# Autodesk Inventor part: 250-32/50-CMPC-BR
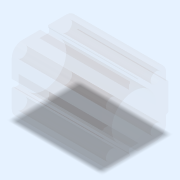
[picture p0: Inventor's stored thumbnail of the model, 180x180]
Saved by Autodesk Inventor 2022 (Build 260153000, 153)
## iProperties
Category: PARTsolutions
Company: METALWORK
Part Number: 250-32/50-CMPC-BR
Material: Generico
Catalog Web Link: www.cadenas.de
Description: CMPC-BR-
Vendor: METALWORK
Document SubType Name: Modeling
Designer: partserver
Manufacturer: METALWORK
Mass: 70.6523 g
Surface Area: 291.919 cm^2
Volume: 70.6523 cm^3
Density: 1 g/cm^3
Appearance: Policarbonato - Fumé
PSOL_IDENT_0: {$CADENAS_DATA\23d-libs\metalwork\actuators\comp_cyl_ser_cmpc\parts\cmpc_barrel.prj},194 {VTYP=3D},{
PSOL_IDENT_1: NB=250-32/50-CMPC-BR},{LINA=250-32/50-CMPC-BR},{NN=CMPC-BR},{DATE=18.06.2021 08:06:07},{GEOMDATE=28.
PSOL_IDENT_2: 10.2014 11:07:41},{VERSION=},{LINEID=50},{WBVAR=TYPE,VE,HUB},{WBNUMERIC=TYPE,HUB}  {NB=250-32/50-CMP
PSOL_IDENT_3: C-BR},{LINA=250-32/50-CMPC-BR},{KT=DUMMY},{IDNR=},{TYPE=25},{TX= 23,'UNITOP male', 24,'UNITOP female'
PSOL_IDENT_4: , 25,'ISO male', 26,'ISO female' },{VE=0},{VX='0','Double-acting','1','Double-acting, through-rod','
PSOL_IDENT_5: 2','Double-acting, perfored through-rod','3','Single-acting, retracted rod','4','Single-acting, exte
PSOL_IDENT_6: nded rod','5','Single acting, through-rod','6','Single-acting, perfored through-rod','A','Double-act
PSOL_IDENT_7: ing, through-rod, non-rotating'},{HUB=50},{DI=32},{A=47.000},{B=32.500},{BB=32.500},{B2=0.000},{D=48
PSOL_IDENT_8: .500},{D1=9},{R1=7.500},{R2=0.500},{H1=6.950},{H2=5.350},{L1=3.550},{L2=1.550},{L3=10.000},{G=44.500
PSOL_IDENT_9: },{HH=14.750},{C1=8.000}
NB: 250-32/50-CMPC-BR
NN: CMPC-BR
NBSYN: $TYPE.$VE.-$DI./$HUB.-CMPC-BR
LINA: 250-32/50-CMPC-BR
CATALOG: Metalwork
TYPE: ISO male
VE: Double-acting
HUB: 50
DI: 32
A: 47
BB: 32.5
B2: 0
D: 48.5
R1: 7.5
R2: 0.5
H1: 6.95
H2: 5.35
L1: 3.55
L2: 1.55
L3: 10
G: 44.5
HH: 14.75
C1: 8
SUPPLIER: METALWORK
ARTICLENO: 250-32/50-CMPC-BR
BOMINFO: 250-32/50-CMPC-BR
CREATOR: CADENAS GmbH
Title: 250-32/50-CMPC-BR
Author: Cadenas PARTsolutions
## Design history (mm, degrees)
sketch "Sketch_1"
  geometry: L1 (-23.5, 16)-(-23.5, 3.075); L2 (-23.1, 2.675)-(-22.15, 2.675); L3 (-21.95, 2.875)-(-21.95, 3.275); L4 (-21.75, 3.475)-(-18.6, 3.475); L5 (-18.4, 3.275)-(-18.4, -3.275); L6 (-18.6, -3.475)-(-21.75, -3.475); L7 (-21.95, -3.275)-(-21.95, -2.875); L8 (-22.15, -2.675)-(-23.1, -2.675); L9 (-23.5, -3.075)-(-23.5, -16); L10 (-16, -23.5)-(-3.075, -23.5); L11 (-2.675, -23.1)-(-2.675, -22.15); L12 (-2.875, -21.95)-(-3.275, -21.95); L13 (-3.475, -21.75)-(-3.475, -18.6); L14 (-3.275, -18.4)-(3.275, -18.4); L15 (3.475, -18.6)-(3.475, -21.75); L16 (3.275, -21.95)-(2.875, -21.95); L17 (2.675, -22.15)-(2.675, -23.1); L18 (3.075, -23.5)-(16, -23.5); L19 (23.5, -16)-(23.5, -10.786); L20 (23.871, -10.303)-(24.629, -10.099); L21 (25, -9.616)-(25, 9.616); L22 (24.629, 10.099)-(23.871, 10.303); L23 (23.5, 10.786)-(23.5, 16); L24 (16, 23.5)-(3.075, 23.5); L25 (2.675, 23.1)-(2.675, 22.15); L26 (2.875, 21.95)-(3.275, 21.95); L27 (3.475, 21.75)-(3.475, 18.6); L28 (3.275, 18.4)-(-3.275, 18.4); L29 (-3.475, 18.6)-(-3.475, 21.75); L30 (-3.275, 21.95)-(-2.875, 21.95); L31 (-2.675, 22.15)-(-2.675, 23.1); L32 (-3.075, 23.5)-(-16, 23.5); C1 r 4 at (16.25, -16.25); C2 r 4 at (-16.25, -16.25); C3 r 16 at (0, 0); C4 r 4 at (-16.25, 16.25); C5 r 4 at (16.25, 16.25); A1 r 7.5 centre (-16, 16) between (-16, 23.5) and (-23.5, 16); A2 r 0.4 centre (-23.1, 3.075) between (-23.5, 3.075) and (-23.1, 2.675); A3 r 0.2 centre (-22.15, 2.875) between (-22.15, 2.675) and (-21.95, 2.875); A4 r 0.2 centre (-21.75, 3.275) between (-21.75, 3.475) and (-21.95, 3.275); A5 r 0.2 centre (-18.6, 3.275) between (-18.4, 3.275) and (-18.6, 3.475); A6 r 0.2 centre (-18.6, -3.275) between (-18.6, -3.475) and (-18.4, -3.275); A7 r 0.2 centre (-21.75, -3.275) between (-21.95, -3.275) and (-21.75, -3.475); A8 r 0.2 centre (-22.15, -2.875) between (-21.95, -2.875) and (-22.15, -2.675); A9 r 0.4 centre (-23.1, -3.075) between (-23.1, -2.675) and (-23.5, -3.075); A10 r 7.5 centre (-16, -16) between (-23.5, -16) and (-16, -23.5); A11 r 0.4 centre (-3.075, -23.1) between (-3.075, -23.5) and (-2.675, -23.1); A12 r 0.2 centre (-2.875, -22.15) between (-2.675, -22.15) and (-2.875, -21.95); A13 r 0.2 centre (-3.275, -21.75) between (-3.475, -21.75) and (-3.275, -21.95); A14 r 0.2 centre (-3.275, -18.6) between (-3.275, -18.4) and (-3.475, -18.6); A15 r 0.2 centre (3.275, -18.6) between (3.475, -18.6) and (3.275, -18.4); A16 r 0.2 centre (3.275, -21.75) between (3.275, -21.95) and (3.475, -21.75); A17 r 0.2 centre (2.875, -22.15) between (2.875, -21.95) and (2.675, -22.15); A18 r 0.4 centre (3.075, -23.1) between (2.675, -23.1) and (3.075, -23.5); A19 r 7.5 centre (16, -16) between (16, -23.5) and (23.5, -16); A20 r 0.5 centre (24, -10.786) between (23.871, -10.303) and (23.5, -10.786); A21 r 0.5 centre (24.5, -9.616) between (24.629, -10.099) and (25, -9.616); A22 r 0.5 centre (24.5, 9.616) between (25, 9.616) and (24.629, 10.099); A23 r 0.5 centre (24, 10.786) between (23.5, 10.786) and (23.871, 10.303); A24 r 7.5 centre (16, 16) between (23.5, 16) and (16, 23.5); A25 r 0.4 centre (3.075, 23.1) between (3.075, 23.5) and (2.675, 23.1); A26 r 0.2 centre (2.875, 22.15) between (2.675, 22.15) and (2.875, 21.95); A27 r 0.2 centre (3.275, 21.75) between (3.475, 21.75) and (3.275, 21.95); A28 r 0.2 centre (3.275, 18.6) between (3.275, 18.4) and (3.475, 18.6); A29 r 0.2 centre (-3.275, 18.6) between (-3.475, 18.6) and (-3.275, 18.4); A30 r 0.2 centre (-3.275, 21.75) between (-3.275, 21.95) and (-3.475, 21.75); A31 r 0.2 centre (-2.875, 22.15) between (-2.875, 21.95) and (-2.675, 22.15); A32 r 0.4 centre (-3.075, 23.1) between (-2.675, 23.1) and (-3.075, 23.5); 5 further points
  constraints: 64 end point, 64 point on circle, 37 centre point
extrude "Extrusion1" join sketch "Sketch_1" distance "d0" = 65; taper "d1" = 0 deg
node "br_l_XY"
node "br_l_YZ"
node "br_l_ZX"
node "br_l_X"
node "br_l_Y"
node "br_l_Z"
node "br_l_Center"
node "br_r_XY"
node "br_r_YZ"
node "br_r_ZX"
node "br_r_X"
node "br_r_Y"
node "br_r_Z"
node "br_r_Center"
node "sensor_left_XY"
node "sensor_left_YZ"
node "sensor_left_ZX"
node "sensor_left_X"
node "sensor_left_Y"
node "sensor_left_Z"
node "sensor_left_Center"
node "sensor_right_XY"
node "sensor_right_YZ"
node "sensor_right_ZX"
node "sensor_right_X"
node "sensor_right_Y"
node "sensor_right_Z"
node "sensor_right_Center"
body "Solid1"
other parameters: "d2" = 0, "d3" = 0, "d4" = 0, "d5" = 0
